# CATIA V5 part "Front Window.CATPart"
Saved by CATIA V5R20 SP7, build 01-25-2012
Part number: Front Window
Bounding box of the stored display mesh (mm): x -25 to 25, y -305 to 305, z -25 to 280
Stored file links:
  E:\#03 University\#02 영남 이공대\#01 2021\#02 여름 방학\#01 Documents\K-Move Page02 ASD01\Front Window.CATPart

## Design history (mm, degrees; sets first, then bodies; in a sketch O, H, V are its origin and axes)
Set1 "Reference Data"
  Point1 "Center Point": (0, 0, 0)
  Plane1 "Plane.1(Z Dir=280mm)": type Offset, RefPlane xy-plane, Offset 280
Body1 (main body)
  Body2 "Main Body"
    Sketch1 on zx-plane, origin (0, 0, 0), H (-1, 0, 0), V (0, 0, 1)
      point P1 (-10, 0)
      line L1 (-10, 0) -> (10, 0)
      line L2 (10, 0) -> (10, 280)
      line L3 (10, 280) -> (-10, 280)
      line L4 (-10, 280) -> (-10, 0)
      reference intersected line E1 through (0, 280) direction (-1, 0) from Plane1
      distance L4 L2 = 20
      coincidence: P1 H, L3 E1
      horizontal: L1 H, L3 H
      vertical: L2 V, L4 V
      symmetry: L4 L2 V
    Pad1: profile Sketch1, direction (0, 1, 0), length 305, mirrored extent
    Fillet1: radius 20, on edge [face of Pad1 from Sketch1.L3 | end face of Pad1]; edge [start face of Pad1 | face of Pad1 from Sketch1.L3]
    Body3 "Hole Boss Body"
      Sketch2 on zx-plane, origin (0, 0, 0), H (-1, 0, 0), V (0, 0, 1)
        circle A1 centre (0, 0) radius 25
        radius A1 = 25
      Pad2: profile Sketch2, direction (0, 1, 0), length 305, mirrored extent
    Assemble1: tool Body3
  Assemble2: tool Body2
  Body4 "Window"
    Sketch3 on yz-plane, origin (0, 0, 0), H (0, 1, 0), V (0, 0, 1)
      point P1 (0, 270)
      line L1 (0, 270) -> (280, 270)
      line L2 (280, 270) -> (280, 40)
      line L3 (280, 40) -> (0, 40)
      line L4 (0, 40) -> (0, 270)
      reference intersected line E1 through (0, 280) direction (-1, 0) from Plane1
      distance E1 L1 = 10
      distance L1 L3 = 230
      distance V L2 = 280
      coincidence: P1 V
      horizontal: L1 H, L3 H
      vertical: L2 V, L4 V
    Pad3: profile Sketch3, direction (1, 0, 0), length 20, opposite side length -3
    Mirror1: of the body so far, about zx-plane
    Mirror2: of the body so far, about yz-plane
    Body5 "Pocket Body"
      Sketch4 on yz-plane, origin (0, 0, 0), H (0, 1, 0), V (0, 0, 1)
        point P1 (0, 30)
        line L1 (0, 30) -> (290, 30)
        line L2 (290, 30) -> (290, -50)
        line L3 (290, -50) -> (0, -50)
        line L4 (0, -50) -> (0, 30)
        distance V L2 = 290
        distance L1 H = 30
        distance L3 H = 50
        coincidence: P1 V
        horizontal: L1 H, L3 H
        vertical: L2 V, L4 V
      Pad4: profile Sketch4, direction (1, 0, 0), length 30, mirrored extent
      Mirror3: of the body so far, about zx-plane
    Assemble3: tool Body5
  Remove1: tool Body4
  Body6 "Hole Boss Body"
    Sketch5 on zx-plane, origin (0, 0, 0), H (-1, 0, 0), V (0, 0, 1)
      circle A1 centre (0, 0) radius 10
      radius A1 = 10
    Pad5: profile Sketch5, direction (0, 1, 0), length 305, mirrored extent
  Assemble4: tool Body6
